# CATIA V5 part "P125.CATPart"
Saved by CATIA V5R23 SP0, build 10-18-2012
Part number: 05-LICP-T02-E-S02-P125
Definition: Poinçon
Bounding box of the stored display mesh (mm): x -12.996 to 12.996, y -12.996 to 12.996, z 0 to 162
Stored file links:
  C:\wamp\www\COURS\CONCEPTION GMP1\TITRE 02-SEMESTRE 2\03-TP7-PRESSE MECANIQUE\eleve\P125.CATPart
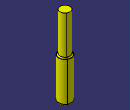
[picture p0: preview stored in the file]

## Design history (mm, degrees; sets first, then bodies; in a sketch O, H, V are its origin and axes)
Body1 (main body)
  Sketch1 on yz-plane, origin (0, 0, 0), H (0, 1, 0), V (0, 0, 1)
    line L1 (0, 0) -> (13, 0)
    line L2 (13, 0) -> (13, 82)
    line L3 (13, 82) -> (10, 82)
    line L4 (10, 82) -> (10, 162)
    line L5 (10, 162) -> (0, 162)
    point P5 (0, 162)
    line L6 (0, 162) -> (0, 0)
    distance L5 L1 = 162
    distance L6 L4 = 10
    distance L2 L6 = 13
    distance L3 L1 = 82
    horizontal: L1 H, L3 H, L5 H
    vertical: L2 V, L4 V, L6 V
    coincidence: P5 V
  Shaft1: profile Sketch1, axis edge of Sketch1, angle 360
  Fillet1: radius 3, on face of Shaft1
  Fillet2: radius 2, on edge [face of Shaft1 | face of Shaft1]
  Sketch2 on zx-plane, origin (0, 0, 0), H (-1, 0, 0), V (0, 0, 1)
    arc A1 centre (0, -5) radius 9 from (-8.9813, -4.4197) to (0, 4) cw
    point P1 (0, -5)
    point P3 (0, 4)
    line L1 (-8.9813, -4.4197) -> (0, -4.4197)
    point P4 (0, -4.4197)
    line L2 (0, -4.4197) -> (0, 4)
    distance L1 H = 4.4197
    distance A1 H = 4
    radius A1 = 9
    coincidence: P3 V, P4 V, L2 P1
    horizontal: L1 H
    vertical: L2 V
  Groove1: profile Sketch2, axis Sketch2.V, angle 360
  Thread1: "M20", diameter 20, depth 60, pitch 2.5, on face of Shaft1, from face of Shaft1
